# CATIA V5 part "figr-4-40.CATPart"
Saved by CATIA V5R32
Part number: Part1
Material "Aluminium": density 2710 kg/m3, Young's modulus 7e+10 Pa, Poisson ratio 0.346, thermal expansion 2.36e-05 1/K
Bounding box of the stored display mesh (mm): x -69.981 to 69.981, y -240 to 0, z -69.908 to 69.908
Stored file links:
  D:\PROJECTS\Project 2022\CATIA V5 6R 2022\Resources\Part Files\c04_catia_v5_6r2022_prt\figr-4-40.CATPart
  C:\Program Files\Dassault Systemes\B32\win_b64\startup\materials\Catalog.CATMaterial
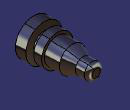
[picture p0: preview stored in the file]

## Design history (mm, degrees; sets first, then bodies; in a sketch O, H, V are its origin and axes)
Body1 (main body), material "Steel"
  Sketch1 on yz-plane, origin (0, 0, 0), H (0, 1, 0), V (0, 0, 1)
    line L1 (0, 0) -> (0, 15.359)
    arc A1 centre (-15.359, 15.359) radius 15.359 from (0, 15.359) to (-15.359, 30.718) ccw
    point P2 (-15.359, 15.359)
    line L2 (-15.359, 30.718) -> (-49.6877, 30.718)
    line L3 (-49.6877, 30.718) -> (-91.8922, 49.6007)
    line L4 (-91.8922, 49.6007) -> (-149.3038, 49.6007)
    line L5 (-149.3038, 49.6007) -> (-149.3038, 60)
    line L6 (-149.3038, 60) -> (-180, 60)
    line L7 (-180, 60) -> (-180, 38.9967)
    line L8 (-180, 38.9967) -> (-200, 40)
    line L9 (-200, 40) -> (-200, 70)
    line L10 (-200, 70) -> (-240, 70)
    line L11 (-240, 70) -> (-240, 0)
    line L12 (-240, 0) -> (0, 0)
    axis line L13 (-300, 0) -> (50, 0)
    vertical: L1 V, L5 V, L7 V, L9 V, L11 V
    tangency: A1 L1, L2 A1, L8 A1, L12 A1, L13 A1
    coincidence: L3 P2
    horizontal: L4 H, L6 H, L10 H, L2 H
    fix: L12
  Shaft1: profile Sketch1, axis Sketch1.H, angle 360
